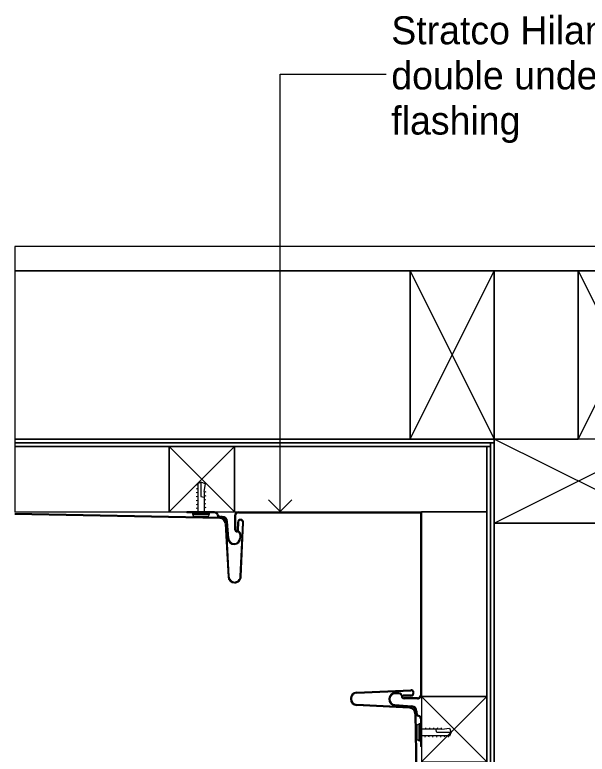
# Model space of a CAD drawing. Extents: x -2.36 to 6.66, y -3.72 to 4.13.
# Drawn here: x 1.9236 to 2.2301, y -2.2717 to -1.876 of the extents above; entities that cross this region are included whole.
import ezdxf

# ---------------------------------------------------------------- set-up
doc = ezdxf.new("R2010")
doc.units = 0
for name, color, linetype in [('A-____-____-IDEN', 7, 'Continuous'), ('A-DETL-____-MEDM', 7, 'Continuous'), ('A-DETL-GENF-OTLN', 7, 'Continuous'), ('A-WALL-____-MCUT', 7, 'Continuous'), ('A-WALL-____-PATT', 7, 'Continuous'), ('A-WALL-FNSH-MCUT', 7, 'Continuous')]:
    doc.layers.add(name, color=color, linetype=linetype)

# ---------------------------------------------------------------- blocks, each defined once
blk = doc.blocks.new('DET_ST_Framing Detail Timber - 35x35 Batten-Detail Flashings - Hiland Nailstrip Corner')
at = {"layer": 'A-DETL-____-MEDM'}
for p, q in [((0.034999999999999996, 0), (0, 0)), ((0, 0), (0, -0.034999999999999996)), ((0.034999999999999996, -0.034999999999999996), (0.034999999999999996, 0)), ((0, -0.034999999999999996), (0.034999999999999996, -0.034999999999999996))]:
    blk.add_line(p, q, dxfattribs=at)
at = {"layer": 'A-DETL-GENF-OTLN'}
for p, q in [((0, -0.034999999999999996), (0.034999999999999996, 4.229949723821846e-18)), ((0.034999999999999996, -0.034999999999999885), (-4.229949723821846e-18, 4.229949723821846e-18))]:
    blk.add_line(p, q, dxfattribs=at)
blk = doc.blocks.new('DET_ST_Framing Detail Timber - 35x35 Batten-V8-Detail Flashings - Hiland Nailstrip Corner')
at = {"layer": 'A-DETL-____-MEDM'}
for p, q in [((0.034999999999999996, 0.034999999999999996), (0, 0.034999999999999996)), ((0, 0.034999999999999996), (0, 0)), ((0.034999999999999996, 0), (0.034999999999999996, 0.034999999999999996)), ((0, 0), (0.034999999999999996, 0))]:
    blk.add_line(p, q, dxfattribs=at)
at = {"layer": 'A-DETL-GENF-OTLN'}
for p, q in [((0, 0.034999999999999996), (0.034999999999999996, 0)), ((0.034999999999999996, 0.034999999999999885), (0, 0))]:
    blk.add_line(p, q, dxfattribs=at)
blk = doc.blocks.new('Detail_Stratco_Hiland_Tray_Nailstrip_Double Underlap Int Corner - Rib Height 38mm_100mm Cover-Detail Flashings - Hiland Nailstrip Corner')
at = {"layer": 'A-DETL-GENF-OTLN'}
for p, q in [((-0.0005000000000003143, 0.1357106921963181), (-0.0005000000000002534, 0.15056515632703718)), ((-2.6547160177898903e-16, 0.15056515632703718), (-0.0005000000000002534, 0.15056515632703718)), ((-3.2649114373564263e-16, 0.1357106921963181), (-2.6547160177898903e-16, 0.15056515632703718)), ((-0.0012874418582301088, 0.14755219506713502), (-0.0022175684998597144, 0.14700529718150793)), ((-0.0022175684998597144, 0.14700529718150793), (-0.0022175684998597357, 0.13899470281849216)), ((-0.0012874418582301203, 0.13844780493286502), (-0.001287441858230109, 0.14755219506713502)), ((-0.0005769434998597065, 0.1470999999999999), (-0.0005769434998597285, 0.13890000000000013)), ((0.015299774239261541, 0.14475), (0.00022305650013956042, 0.14475000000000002)), ((0.002009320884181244, 0.14475000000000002), (0.0017713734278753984, 0.1455)), ((0.004107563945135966, 0.14475000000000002), (0.0038696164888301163, 0.14550000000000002)), ((0.006205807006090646, 0.14475), (0.005967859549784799, 0.1455)), ((0.008320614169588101, 0.14299999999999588), (0.00781847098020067, 0.14125)), ((0.008304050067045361, 0.14475000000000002), (0.008066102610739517, 0.1455)), ((0.015936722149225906, 0.14299999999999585), (0.008320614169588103, 0.14299999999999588)), ((0.010402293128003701, 0.14475), (0.010164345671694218, 0.1455)), ((0.012500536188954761, 0.14475), (0.012262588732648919, 0.1455)), ((0.014598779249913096, 0.14474999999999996), (0.01436083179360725, 0.1455)), ((0.01509158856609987, 0.14067801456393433), (0.015936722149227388, 0.14299999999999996)), ((0.015299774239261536, 0.14475), (0.01593672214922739, 0.14299999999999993)), ((-0.0022175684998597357, 0.1389947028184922), (-0.0012776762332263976, 0.1384420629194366)), ((0.011021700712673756, 0.14125), (0.00022305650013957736, 0.14125000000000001)), ((0.0022833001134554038, 0.14049999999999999), (0.0020453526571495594, 0.14125)), ((0.004381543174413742, 0.1405), (0.0041435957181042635, 0.14125)), ((0.006479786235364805, 0.14049999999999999), (0.0062418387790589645, 0.14125)), ((0.008578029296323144, 0.14049999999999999), (0.008340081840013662, 0.14125)), ((0.010676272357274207, 0.14049999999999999), (0.01043832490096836, 0.14125)), ((0.011021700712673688, 0.14125), (0.01509158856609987, 0.14067801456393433)), ((-0.002913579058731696, 0.13162103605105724), (-0.002913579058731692, 0.1325703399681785)), ((-0.002413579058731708, 0.13162103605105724), (-0.0024135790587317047, 0.1325703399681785)), ((-0.014220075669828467, 0.12863421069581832), (-0.005078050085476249, 0.12929457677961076)), ((-0.014184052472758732, 0.12813551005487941), (-0.0050420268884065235, 0.12879587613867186)), ((-0.0020000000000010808, 0.12500000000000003), (-0.009238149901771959, 0.12500000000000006)), ((-0.0020000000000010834, 0.12450000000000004), (-0.009238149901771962, 0.12450000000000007)), ((-0.0005000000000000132, 0.12300000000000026), (-0.0005000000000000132, 0.025500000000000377)), ((0, 0.12300000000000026), (0, 0.025000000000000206)), ((-0.012056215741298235, 0.12229429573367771), (-0.013973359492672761, 0.12229429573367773)), ((-0.012056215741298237, 0.12179429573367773), (-0.013973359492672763, 0.12179429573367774)), ((-0.10363421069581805, 0.0392200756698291), (-0.10429457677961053, 0.030078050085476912)), ((-0.10313551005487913, 0.03918405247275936), (-0.10379587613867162, 0.03004202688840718)), ((-0.09729429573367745, 0.03705621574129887), (-0.09729429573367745, 0.03897335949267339)), ((-0.09679429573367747, 0.03705621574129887), (-0.09679429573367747, 0.03897335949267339)), ((-0.09999999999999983, 0.027000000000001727), (-0.09999999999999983, 0.03423814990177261)), ((-0.09949999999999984, 0.027000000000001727), (-0.09949999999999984, 0.03423814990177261)), ((-0.10662103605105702, 0.027913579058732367), (-0.10757033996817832, 0.027913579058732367)), ((-0.11071069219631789, 0.025500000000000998), (-0.12556515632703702, 0.025500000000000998)), ((-0.12556515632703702, 0.025000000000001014), (-0.12556515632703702, 0.025500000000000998)), ((-0.11071069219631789, 0.025000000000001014), (-0.12556515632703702, 0.025000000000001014)), ((-0.12255219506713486, 0.026287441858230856), (-0.1220052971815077, 0.027217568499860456)), ((-0.11344780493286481, 0.026287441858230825), (-0.12255219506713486, 0.026287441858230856)), ((-0.12209999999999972, 0.025576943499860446), (-0.11389999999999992, 0.025576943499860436)), ((-0.1220052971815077, 0.027217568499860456), (-0.11399470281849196, 0.027217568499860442)), ((-0.11974999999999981, 0.00970022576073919), (-0.1197499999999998, 0.024776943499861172)), ((-0.11624999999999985, 0.013978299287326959), (-0.11624999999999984, 0.024776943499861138)), ((-0.11399470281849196, 0.027217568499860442), (-0.11344206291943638, 0.0262776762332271)), ((-0.10662103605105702, 0.027413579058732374), (-0.10757033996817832, 0.027413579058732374)), ((-0.0005000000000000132, 0.025500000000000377), (-0.09799999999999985, 0.025500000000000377)), ((0, 0.025000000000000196), (-0.09799999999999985, 0.025000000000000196)), ((-0.1197499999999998, 0.02299067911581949), (-0.1204999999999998, 0.023228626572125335)), ((-0.1197499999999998, 0.02089243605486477), (-0.12049999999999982, 0.021130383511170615)), ((-0.11549999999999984, 0.02271669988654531), (-0.11624999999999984, 0.022954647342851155)), ((-0.11549999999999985, 0.02061845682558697), (-0.11624999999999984, 0.02085640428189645)), ((-0.1197499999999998, 0.018794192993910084), (-0.12049999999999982, 0.019032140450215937)), ((-0.11974999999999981, 0.016695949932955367), (-0.12049999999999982, 0.01693389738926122)), ((-0.11799999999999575, 0.016679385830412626), (-0.11624999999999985, 0.017181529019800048)), ((-0.11799999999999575, 0.009063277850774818), (-0.11799999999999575, 0.016679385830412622)), ((-0.11549999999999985, 0.01852021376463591), (-0.11624999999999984, 0.018758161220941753)), ((-0.11549999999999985, 0.016421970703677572), (-0.11624999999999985, 0.016659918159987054)), ((-0.11974999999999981, 0.014597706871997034), (-0.12049999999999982, 0.014835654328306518)), ((-0.11974999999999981, 0.01249946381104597), (-0.12049999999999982, 0.012737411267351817)), ((-0.11549999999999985, 0.014323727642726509), (-0.11624999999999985, 0.014561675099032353)), ((-0.11624999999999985, 0.013978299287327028), (-0.1156780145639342, 0.009908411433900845)), ((-0.11974999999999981, 0.010401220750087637), (-0.12049999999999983, 0.010639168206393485)), ((-0.11974999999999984, 0.009700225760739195), (-0.11799999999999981, 0.009063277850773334)), ((-0.1156780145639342, 0.009908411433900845), (-0.11799999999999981, 0.009063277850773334))]:
    blk.add_line(p, q, dxfattribs=at)
for centre, radius, start, end in [((-0.0010769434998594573, 0.1470999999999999), 0.0005000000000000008, 359.9999999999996, 113.66982389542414), ((0.00022305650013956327, 0.14554999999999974), 0.0008000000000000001, 179.99999999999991, 269.99999999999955), ((-0.001076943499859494, 0.13890000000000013), 0.0005000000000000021, 246.33017610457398, 359.99999999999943), ((0.00022305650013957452, 0.1404500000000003), 0.0008, 89.99999999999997, 179.99999999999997), ((-0.001903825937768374, 0.1357106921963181), 0.0014038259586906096, 284.91043283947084, 0), ((-0.001903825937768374, 0.1357106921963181), 0.0019038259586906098, 284.9104328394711, 0), ((-0.005246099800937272, 0.13162103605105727), 0.0023325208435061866, 274.1315338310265, 0), ((-0.005246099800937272, 0.13162103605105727), 0.002832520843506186, 274.1315338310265, 359.9999999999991), ((-0.0010676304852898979, 0.1325703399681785), 0.001845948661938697, 104.91043283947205, 180.00000000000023), ((-0.0010676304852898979, 0.1325703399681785), 0.0013459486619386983, 104.91043283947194, 180.00000000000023), ((-0.013973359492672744, 0.12521870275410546), 0.003424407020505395, 94.13153383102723, 269.9999999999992), ((-0.013973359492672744, 0.12521870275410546), 0.0029244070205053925, 94.13153383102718, 269.9999999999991), ((-0.01205621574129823, 0.1236942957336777), 0.0013999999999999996, 269.99999999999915, 350.84548951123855), ((-0.01205621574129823, 0.1236942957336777), 0.001900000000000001, 269.9999999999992, 352.83254480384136), ((-0.009238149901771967, 0.12356130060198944), 0.0014386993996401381, 89.99999999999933, 183.57624011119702), ((-0.009238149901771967, 0.12356130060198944), 0.0009386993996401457, 89.9999999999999, 186.36507997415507), ((-0.0020000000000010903, 0.12300000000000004), 0.002000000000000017, 359.9999999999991, 89.99999999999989), ((-0.0020000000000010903, 0.12300000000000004), 0.001500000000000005, 1.9655827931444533e-12, 89.9999999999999), ((-0.1002187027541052, 0.03897335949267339), 0.0034244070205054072, 0, 175.86846616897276), ((-0.1002187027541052, 0.03897335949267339), 0.002924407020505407, 0, 175.8684661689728), ((-0.09856130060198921, 0.034238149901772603), 0.0014386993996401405, 86.42375988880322, 179.99999999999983), ((-0.09869429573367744, 0.03705621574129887), 0.0013999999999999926, 279.1545104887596, 0), ((-0.09869429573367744, 0.03705621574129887), 0.0018999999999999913, 277.16745519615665, 0), ((-0.09856130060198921, 0.034238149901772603), 0.0009386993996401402, 83.63492002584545, 179.9999999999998), ((-0.10757033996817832, 0.026067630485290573), 0.001845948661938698, 89.99999999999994, 165.08956716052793), ((-0.10662103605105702, 0.030246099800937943), 0.0023325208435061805, 269.99999999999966, 355.8684661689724), ((-0.10662103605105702, 0.030246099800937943), 0.0028325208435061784, 269.99999999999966, 355.8684661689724), ((-0.12209999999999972, 0.0260769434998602), 0.0005000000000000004, 156.330176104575, 269.99999999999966), ((-0.12054999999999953, 0.024776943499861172), 0.0008000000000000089, 0, 90), ((-0.11545000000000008, 0.024776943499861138), 0.0008000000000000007, 89.99999999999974, 179.99999999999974), ((-0.11389999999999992, 0.0260769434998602), 0.0005000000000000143, 269.99999999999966, 23.669823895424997), ((-0.11071069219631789, 0.02690382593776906), 0.0014038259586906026, 269.99999999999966, 345.08956716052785), ((-0.11071069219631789, 0.02690382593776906), 0.0019038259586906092, 269.99999999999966, 345.08956716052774), ((-0.10757033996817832, 0.026067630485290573), 0.0013459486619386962, 89.99999999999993, 165.0895671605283), ((-0.09799999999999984, 0.027000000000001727), 0.0020000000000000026, 179.99999999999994, 270.0000000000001), ((-0.09799999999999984, 0.027000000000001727), 0.0015000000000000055, 179.99999999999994, 269.9999999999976)]:
    blk.add_arc(centre, radius, start, end, dxfattribs=at)
blk = doc.blocks.new('Detail Repeating_Stratco_Hiland_Tray_Nailstrip - Rib Height 38mm_165mm Coverage-Detail Flashings - Hiland Nailstrip Corner')
at = {"layer": 'A-DETL-____-MEDM'}
for p, q in [((-0.0035190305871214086, 0.03458502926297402), (-0.00482759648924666, 0.005699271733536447)), ((-0.0030193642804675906, 0.03456634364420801), (-0.004327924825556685, 0.005680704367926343)), ((0.0044987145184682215, 0.006345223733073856), (0.003015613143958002, 0.034638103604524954)), ((0.004998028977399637, 0.006371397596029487), (0.00351492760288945, 0.03466427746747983)), ((-0.001993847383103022, 0.005613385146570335), (-0.001867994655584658, 0.009787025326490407)), ((-0.0013682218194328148, 0.009771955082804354), (-0.001867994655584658, 0.009787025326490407)), ((-0.0014940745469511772, 0.005598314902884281), (-0.0013682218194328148, 0.009771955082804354)), ((0.008000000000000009, 0.0035284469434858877), (0.1177051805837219, 0.0013847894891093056)), ((0.00800101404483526, 0.0030284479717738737), (0.11770518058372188, 0.000884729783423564))]:
    blk.add_line(p, q, dxfattribs=at)
for centre, radius, start, end in [((-3.378274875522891e-07, 0.034479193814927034), 0.003520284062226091, 88.27177070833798, 178.27717358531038), ((-3.378274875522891e-07, 0.034479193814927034), 0.003020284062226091, 88.27089304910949, 178.3465096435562), ((3.394205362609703e-07, 0.03448004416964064), 0.0030194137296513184, 3.0006752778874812, 88.2832516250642), ((3.394205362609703e-07, 0.03448004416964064), 0.003519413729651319, 3.000675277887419, 88.28237372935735), ((-0.0031614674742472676, 0.00564870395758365), 0.0016668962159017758, 178.26158059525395, 268.3043897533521), ((-0.0031614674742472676, 0.00564870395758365), 0.0011668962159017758, 178.42855061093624, 268.3144664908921), ((-0.003160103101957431, 0.005648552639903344), 0.0016667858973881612, 268.257356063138, 358.2728157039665), ((-0.003160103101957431, 0.005648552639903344), 0.0011667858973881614, 268.2472785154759, 358.2728157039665), ((0.007993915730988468, 0.006528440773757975), 0.003499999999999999, 183.00067527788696, 270.11620105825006), ((0.007993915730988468, 0.006528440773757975), 0.0029999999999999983, 186.00067527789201, 270.1162010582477)]:
    blk.add_arc(centre, radius, start, end, dxfattribs=at)
blk = doc.blocks.new('Detail Repeating_Stratco_Hiland_Tray_Nailstrip - Rib Height 38mm_165mm Coverage-V9-Detail Flashings - Hiland Nailstrip Corner')
at = {"layer": 'A-DETL-____-MEDM'}
for p, q in [((0.008000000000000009, -0.0035284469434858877), (0.16297544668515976, -0.0005002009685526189)), ((0.00800101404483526, -0.0030284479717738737), (0.16296726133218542, -2.6797304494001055e-07)), ((-0.0035190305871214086, -0.03458502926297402), (-0.00482759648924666, -0.005699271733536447)), ((-0.0030193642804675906, -0.03456634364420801), (-0.004327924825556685, -0.005680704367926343)), ((-0.001993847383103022, -0.005613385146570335), (-0.001867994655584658, -0.009787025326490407)), ((-0.0014940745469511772, -0.005598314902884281), (-0.0013682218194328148, -0.009771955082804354)), ((0.0044987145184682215, -0.006345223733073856), (0.003015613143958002, -0.034638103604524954)), ((0.004998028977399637, -0.006371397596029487), (0.00351492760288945, -0.03466427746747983)), ((-0.0013682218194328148, -0.009771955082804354), (-0.001867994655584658, -0.009787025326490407))]:
    blk.add_line(p, q, dxfattribs=at)
for centre, radius, start, end in [((0.007993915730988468, -0.006528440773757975), 0.003499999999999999, 89.88379894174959, 176.9993247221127), ((0.007993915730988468, -0.006528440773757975), 0.0029999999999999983, 89.88379894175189, 173.99932472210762), ((-0.0031614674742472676, -0.00564870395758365), 0.0016668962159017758, 91.69561024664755, 181.73841940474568), ((-0.0031614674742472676, -0.00564870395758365), 0.0011668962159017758, 91.68553350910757, 181.57144938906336), ((-0.003160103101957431, -0.005648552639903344), 0.0016667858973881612, 1.7271842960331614, 91.74264393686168), ((-0.003160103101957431, -0.005648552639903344), 0.0011667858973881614, 1.727184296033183, 91.75272148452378), ((-3.378274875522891e-07, -0.034479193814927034), 0.003520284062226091, 181.72282641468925, 271.7282292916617), ((-3.378274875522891e-07, -0.034479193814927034), 0.003020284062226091, 181.65349035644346, 271.7291069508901), ((3.394205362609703e-07, -0.03448004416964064), 0.0030194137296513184, 271.71674837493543, 356.9993247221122), ((3.394205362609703e-07, -0.03448004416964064), 0.003519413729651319, 271.7176262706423, 356.9993247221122)]:
    blk.add_arc(centre, radius, start, end, dxfattribs=at)
blk = doc.blocks.new('DET_ST_Framing Detail Timber - 45x90-Detail Flashings - Hiland Nailstrip Corner')
at = {"layer": 'A-DETL-____-MEDM'}
for p, q in [((0.09000000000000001, 0.045000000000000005), (0, 0.045000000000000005)), ((0.09000000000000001, 0), (0.09000000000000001, 0.045000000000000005)), ((0, 0), (0.09000000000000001, 0))]:
    blk.add_line(p, q, dxfattribs=at)
at = {"layer": 'A-DETL-GENF-OTLN'}
for p, q in [((0, 0.04500000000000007), (0.09000000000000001, 0)), ((0.09000000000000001, 0.045000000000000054), (0, 0))]:
    blk.add_line(p, q, dxfattribs=at)
blk = doc.blocks.new('DET_ST_Framing Detail Timber - 45x90-V12-Detail Flashings - Hiland Nailstrip Corner')
at = {"layer": 'A-DETL-____-MEDM'}
for p, q in [((0.09000000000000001, 0.045000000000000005), (0, 0.045000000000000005)), ((0, 0.045000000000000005), (0, 0)), ((0.09000000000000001, 0), (0.09000000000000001, 0.045000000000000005)), ((0, 0), (0.09000000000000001, 0))]:
    blk.add_line(p, q, dxfattribs=at)
at = {"layer": 'A-DETL-GENF-OTLN'}
for p, q in [((0, 0.04500000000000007), (0.09000000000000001, 0)), ((0.09000000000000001, 0.045000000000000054), (0, 0))]:
    blk.add_line(p, q, dxfattribs=at)

msp = doc.modelspace()

# ---------------------------------------------------------------- linework, layer by layer
at = {"layer": 'A-____-____-IDEN'}
for p, q in [((2.0657731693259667, -1.9078018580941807), (2.122513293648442, -1.9078018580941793)), ((2.0657731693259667, -2.141710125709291), (2.0657731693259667, -1.9078018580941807)), ((2.0657731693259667, -2.141710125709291), (2.0595231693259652, -2.135460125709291)), ((2.0657731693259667, -2.141710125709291), (2.0720231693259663, -2.135460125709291))]:
    msp.add_line(p, q, dxfattribs=at)
at = {"layer": 'A-WALL-____-MCUT'}
for p, q in [((2.13534232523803, -2.013000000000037), (1.9236371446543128, -2.0130000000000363)), ((2.2253423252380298, -2.013000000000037), (2.1803423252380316, -2.013000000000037)), ((2.13534232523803, -2.103000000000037), (1.9236371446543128, -2.103000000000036)), ((2.1783423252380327, -2.1050000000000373), (1.9236371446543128, -2.1050000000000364)), ((2.1783423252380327, -2.105000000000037), (2.1783423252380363, -2.700000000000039)), ((2.0063423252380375, -2.1070000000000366), (1.9236371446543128, -2.1070000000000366)), ((2.1763423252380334, -2.107000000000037), (2.041342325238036, -2.1070000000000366)), ((2.1763423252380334, -2.1070000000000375), (2.1763423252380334, -2.2407500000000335)), ((1.9236371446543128, -2.1420000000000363), (2.0063423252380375, -2.1420000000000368)), ((2.041342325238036, -2.1420000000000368), (2.1413423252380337, -2.142000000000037)), ((2.1413423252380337, -2.142000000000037), (2.1413423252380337, -2.240750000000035)), ((2.180342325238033, -2.1480000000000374), (2.180342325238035, -2.7000000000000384))]:
    msp.add_line(p, q, dxfattribs=at)
at = {"layer": 'A-WALL-____-PATT'}
for p, q in [((2.283342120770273, -2.000000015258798), (1.9236373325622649, -2.000000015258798)), ((1.9236373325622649, -2.000000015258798), (1.9236373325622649, -2.0129999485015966)), ((1.9236373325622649, -2.0129999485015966), (2.2703417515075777, -2.0129999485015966)), ((2.135342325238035, -2.0130000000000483), (1.9236373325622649, -2.0130000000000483)), ((1.9236373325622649, -2.0130000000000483), (1.9236373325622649, -2.0643007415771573)), ((2.135342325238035, -2.1029999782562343), (2.135342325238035, -2.0130000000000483)), ((2.225342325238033, -2.0130000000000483), (2.180342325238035, -2.0129999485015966)), ((2.180342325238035, -2.0129999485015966), (2.1803425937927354, -2.1029999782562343)), ((2.225342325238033, -2.1029999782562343), (2.225342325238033, -2.0130000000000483)), ((1.9236373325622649, -2.0643007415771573), (1.9236373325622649, -2.1029999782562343)), ((1.9236373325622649, -2.1029999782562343), (2.135342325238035, -2.1029999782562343)), ((2.180342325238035, -2.1030000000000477), (1.9236373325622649, -2.1030000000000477)), ((1.9236373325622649, -2.1030000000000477), (1.9236373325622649, -2.105000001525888)), ((1.9236373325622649, -2.105000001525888), (2.1783427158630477, -2.105000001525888)), ((2.1783427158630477, -2.105000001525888), (1.9236373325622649, -2.105000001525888)), ((1.9236373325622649, -2.105000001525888), (1.9236373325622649, -2.107000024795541)), ((2.180342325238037, -2.105000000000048), (2.1783423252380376, -2.105000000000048)), ((2.1783423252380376, -2.105000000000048), (2.17834232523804, -2.70000000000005)), ((2.1783427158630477, -2.105000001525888), (2.180342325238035, -2.105000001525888)), ((2.1783427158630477, -2.107000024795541), (2.1783427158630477, -2.105000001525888)), ((2.180342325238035, -2.105000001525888), (2.180342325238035, -2.1030000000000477)), ((2.1803423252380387, -2.70000000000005), (2.180342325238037, -2.105000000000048)), ((2.1803425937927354, -2.1029999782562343), (2.210110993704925, -2.1029999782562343)), ((2.210110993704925, -2.1029999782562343), (2.225342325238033, -2.1029999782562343)), ((2.006342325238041, -2.107000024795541), (1.9236373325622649, -2.107000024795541)), ((1.9236373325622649, -2.107000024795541), (1.9236373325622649, -2.142000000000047)), ((1.9236373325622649, -2.107000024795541), (2.17634283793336, -2.107000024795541)), ((2.006342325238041, -2.1420000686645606), (2.006342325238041, -2.107000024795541)), ((2.17634283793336, -2.107000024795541), (2.041342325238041, -2.107000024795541)), ((2.041342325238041, -2.107000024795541), (2.041342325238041, -2.142000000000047)), ((2.1783423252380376, -2.1070000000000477), (2.176342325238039, -2.1070000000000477)), ((2.176342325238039, -2.1070000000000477), (2.176342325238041, -2.6043289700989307)), ((2.17634283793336, -2.1420000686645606), (2.17634283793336, -2.107000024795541)), ((2.17634283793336, -2.107000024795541), (2.1783427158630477, -2.107000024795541)), ((2.17834232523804, -2.70000000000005), (2.1783423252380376, -2.1070000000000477)), ((1.9236373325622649, -2.142000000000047), (2.006342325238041, -2.1420000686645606)), ((2.041342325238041, -2.142000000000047), (2.1413426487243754, -2.1420000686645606)), ((2.176342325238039, -2.142000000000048), (2.1413423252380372, -2.142000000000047)), ((2.1413423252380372, -2.142000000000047), (2.1413423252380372, -2.2002536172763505)), ((2.1413426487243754, -2.1420000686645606), (2.17634283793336, -2.1420000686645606)), ((2.176342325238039, -2.240750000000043), (2.176342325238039, -2.142000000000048)), ((2.2703423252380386, -2.148000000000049), (2.180342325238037, -2.148000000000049)), ((2.180342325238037, -2.148000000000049), (2.1803423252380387, -2.70000000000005)), ((2.1413423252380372, -2.2002536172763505), (2.1413423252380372, -2.240750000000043)), ((2.1413423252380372, -2.240750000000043), (2.176342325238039, -2.240750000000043))]:
    msp.add_line(p, q, dxfattribs=at)
at = {"layer": 'A-WALL-FNSH-MCUT'}
msp.add_line((2.283342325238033, -2.0000000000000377), (1.9236371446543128, -2.0000000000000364), dxfattribs=at)

# ---------------------------------------------------------------- block references
at = {"layer": 'A-DETL-GENF-OTLN'}
for name, p, rotation in [('DET_ST_Framing Detail Timber - 45x90-V12-Detail Flashings - Hiland Nailstrip Corner', (2.1803423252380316, -2.103000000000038), 89.9999999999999), ('DET_ST_Framing Detail Timber - 45x90-Detail Flashings - Hiland Nailstrip Corner', (2.2703423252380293, -2.103000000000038), 89.9999999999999), ('DET_ST_Framing Detail Timber - 45x90-V12-Detail Flashings - Hiland Nailstrip Corner', (2.2703423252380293, -2.103000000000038), 180), ('Detail_Stratco_Hiland_Tray_Nailstrip_Double Underlap Int Corner - Rib Height 38mm_100mm Cover-Detail Flashings - Hiland Nailstrip Corner', (2.166342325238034, -2.1420000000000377), 89.9999999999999), ('Detail Repeating_Stratco_Hiland_Tray_Nailstrip - Rib Height 38mm_165mm Coverage-Detail Flashings - Hiland Nailstrip Corner', (2.041342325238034, -2.1420000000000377), 180), ('Detail Repeating_Stratco_Hiland_Tray_Nailstrip - Rib Height 38mm_165mm Coverage-V9-Detail Flashings - Hiland Nailstrip Corner', (2.1413423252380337, -2.2420000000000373), -89.99999999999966), ('DET_ST_Framing Detail Timber - 35x35 Batten-Detail Flashings - Hiland Nailstrip Corner', (2.1413423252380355, -2.275750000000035), 90.00000000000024)]:
    msp.add_blockref(name, p, dxfattribs=dict(at, rotation=rotation))
msp.add_blockref('DET_ST_Framing Detail Timber - 35x35 Batten-V8-Detail Flashings - Hiland Nailstrip Corner', (2.0063423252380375, -2.142000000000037), dxfattribs=at)

# ---------------------------------------------------------------- texts
at = {"layer": 'A-____-____-IDEN'}
for s, p in [('Stratco Hiland Tray Nailstrip', (2.125227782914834, -1.8917513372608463)), ('double underlap internal corner', (2.125227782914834, -1.915894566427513)), ('flashing', (2.125227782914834, -1.9400377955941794))]:
    msp.add_text(s, height=0.014999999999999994, dxfattribs=at).set_placement(p)

doc.saveas('drawing.dxf')
